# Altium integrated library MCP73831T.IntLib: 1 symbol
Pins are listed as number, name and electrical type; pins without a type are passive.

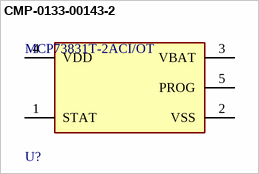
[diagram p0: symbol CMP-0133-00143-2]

## CMP-0133-00143-2
designator U?, comment MCP73831T-2ACI/OT
IC CONTROLLR LI-ION 4.2V SOT23-5; Max Power Dissipation: 1.54W; Output Current: 500mA; Max Output Voltage: 4.5V; Number of Outputs: 1; Min Output Voltage: 4.168V; Min Supply Voltage: 3.75V; Max Input Voltage: 6V; Voltage Rating: 4.534V; Drain to Source Resistance: 350mR
footprint FP-C04-091-OT-IPC_C
footprint FP-C04-091-OT-IPC_B
footprint FP-C04-091-OT-MFG
footprint FP-C04-091-OT-IPC_A
pins: 1 STAT, 2 VSS (power), 3 VBAT (power), 4 VDD (power), 5 PROG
